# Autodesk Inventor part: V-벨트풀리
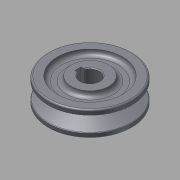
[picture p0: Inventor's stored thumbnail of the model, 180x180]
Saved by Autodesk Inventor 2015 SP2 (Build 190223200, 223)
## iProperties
Created: 2015-12
Part Number: V-벨트풀리
Material: 강철, 연강
Document SubType Name: Modeling
Designer: mdu
Density: 7.86 g/cm^3
Appearance: 강철
CustomPartVersion: 1
Author: mdu
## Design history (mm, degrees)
sketch "주 스케치"
  geometry: L1 (0, 16)-(27, 16); L2 (27, 16)-(27, 12.861); L3 (27, 12.861)-(16, 9.498); L4 (16, 9.498)-(16, 6.502); L5 (16, 6.502)-(27, 3.139); L6 (27, 3.139)-(27, 0); L7 (27, 0)-(0, 0); L8 (25, 12.25)-(25, 3.75); L9 (16, 8)-(25, 8); L10 (27, 12.861)-(27, 3.139); L11 (0, -3)-(0, 18) reference; L12 (0, 0)-(0, 16)
  constraints: 22 end point, 5 perpendicular, 2 collinear, 2 midpoint, 2 point on line, 1 parallel
  dimensions: "d0" = 8.5 distance of L8.start L8.end (= da_Bw); "d1" = 34 deg angle of L3 L5 (= da_Alfa); "d2" = 2 distance between parallel lines of L2 L8 (= da_c); "d6" = 16 distance between parallel lines of L7 L1 (computed from d5, da_ng, da_Sg); "d21" = 50 diameter of L8 L11 (= da_Dw); "d25" = 11 distance between parallel lines of L4 L10 (= da_Hd); "d27" = 8 distance between parallel lines of L7 L9 (= da_Se)
node "벨트 평면"
revolve "본체" stored, may be unused: angle "d7" = 90 deg
revolve "그루브" stored, may be unused: angle "d15" = 90 deg
feature "허브 키홈"
fillet "모깎기3" dims "d28" = 0.5, "d29" = 1, "d30" = 1
sketch "스케치2"
  geometry: C1 r 12 at (0, 0); C2 r 21 at (0, 0); 1 further point
  constraints: 2 centre point, 2 coincident
  dimensions: "d31" = 24 diameter of C1; "d32" = 42 diameter of C2
extrude "돌출1" cut sketch "스케치2" distance "d33" = 3; taper "d34" = 0 deg
fillet "모깎기4" dims "d35" = 3
node "작업 평면2"
chamfer "모따기1" distance "d36" = 0.5; stored, may be unused: second distance "d37" = 2, angle "d38" = 45 deg
body "Solid1"
pattern_linear "그루브 패턴" dims "d18" = 12 (= da_Sg)
mirror "대칭1"
other parameters: "d5" = 8 (= da_Se), "da_Bw" = 8.5 [user parameter; used in 1 equation term], "da_Alfa" = 34 deg [user parameter; used in 1 equation term], "da_c" = 2 [user parameter; used in 1 equation term], "da_Dw" = 50 [user parameter; used in 1 equation term], "da_Hd" = 11 [user parameter; used in 1 equation term], "da_Se" = 8 [user parameter; used in 2 equation terms], "da_Sg" = 12 [user parameter; used in 2 equation terms], "da_r1" = 0 [user parameter], "da_r2" = 0 [user parameter], "d24" = 0, "d26" = 0
